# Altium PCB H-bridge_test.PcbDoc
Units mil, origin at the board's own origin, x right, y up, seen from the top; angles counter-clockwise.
Board outline 2420 x 2070 mil, 2 copper layers (Top Layer, Bottom Layer); 25 components, 24 nets, 89 pads, 74 vias.
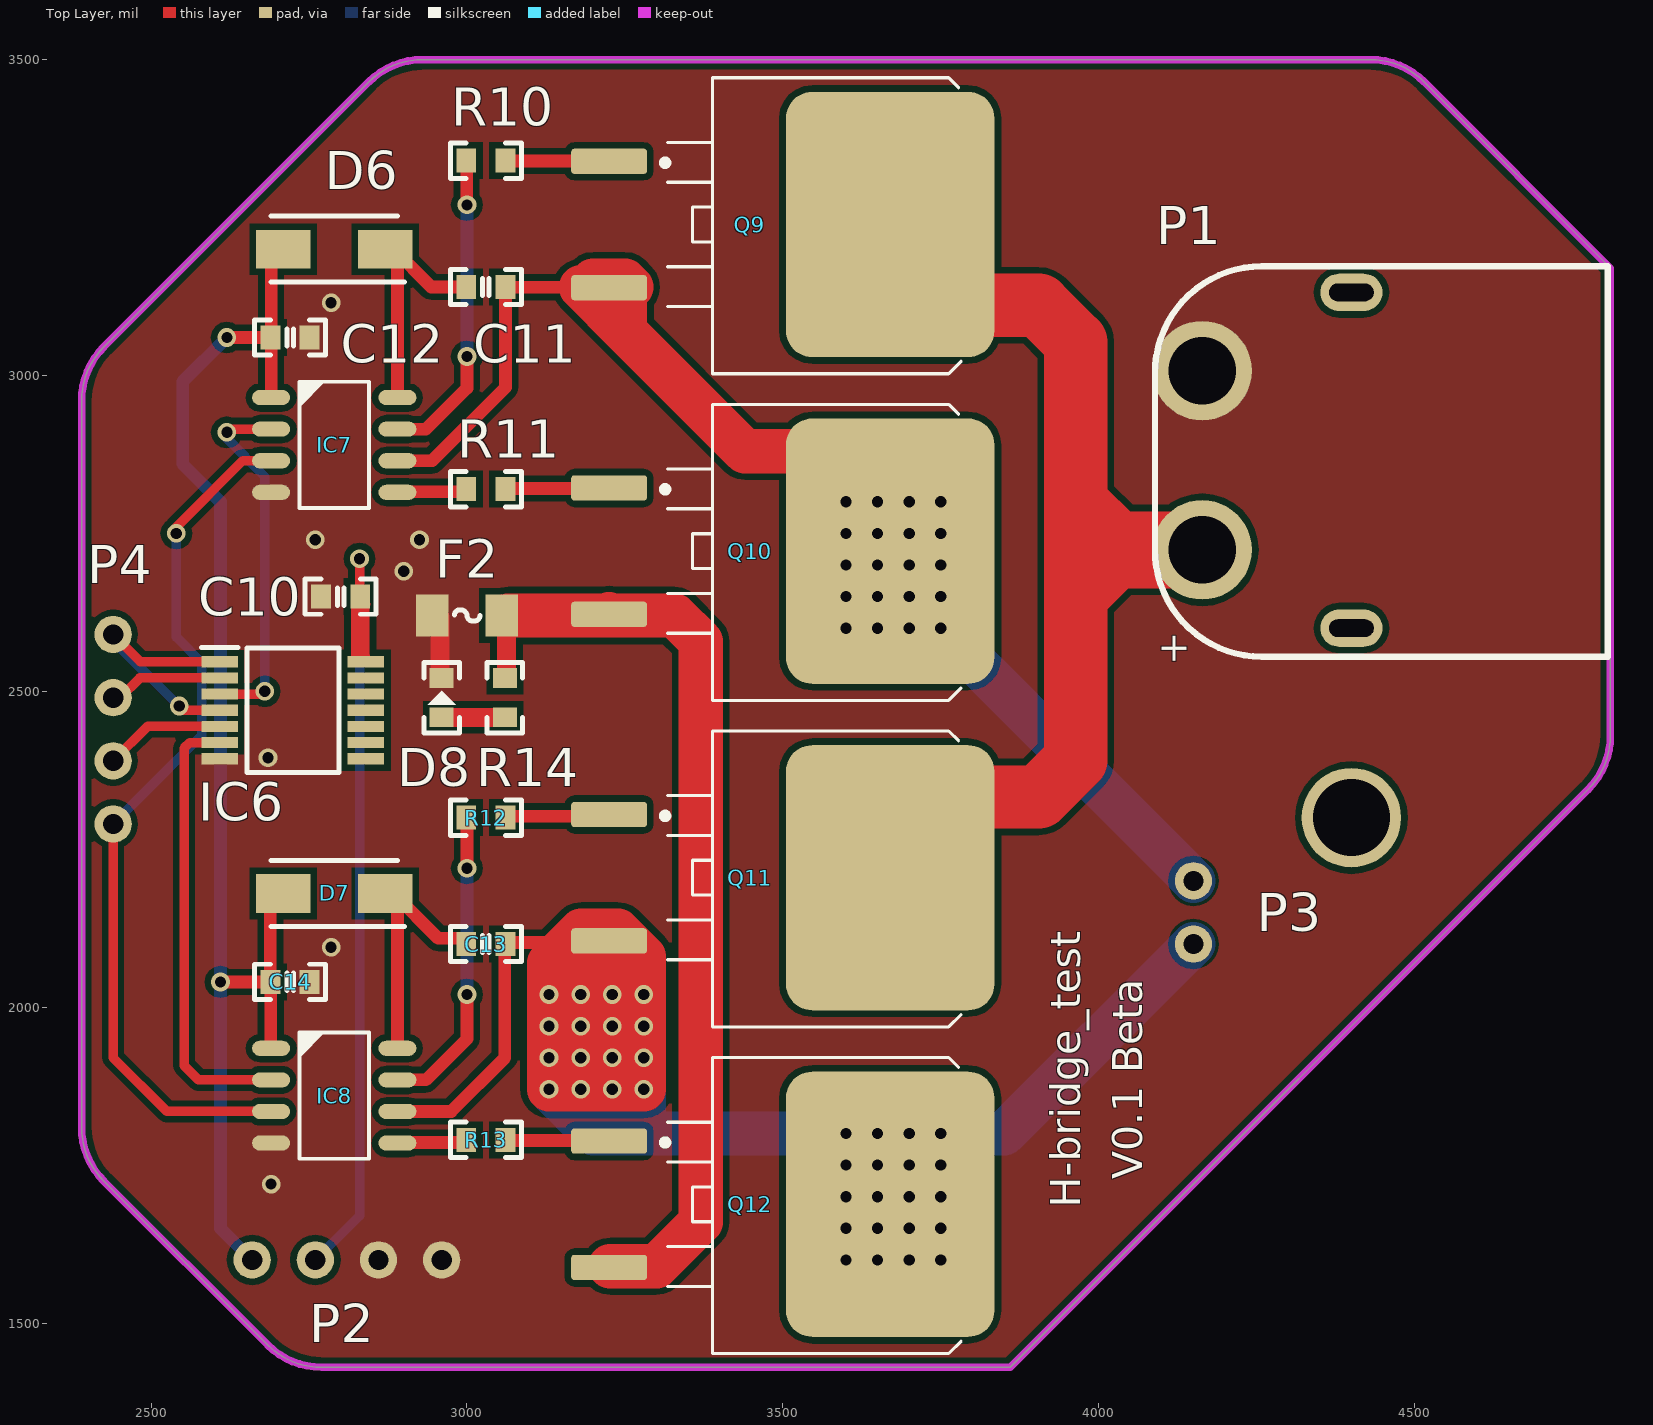
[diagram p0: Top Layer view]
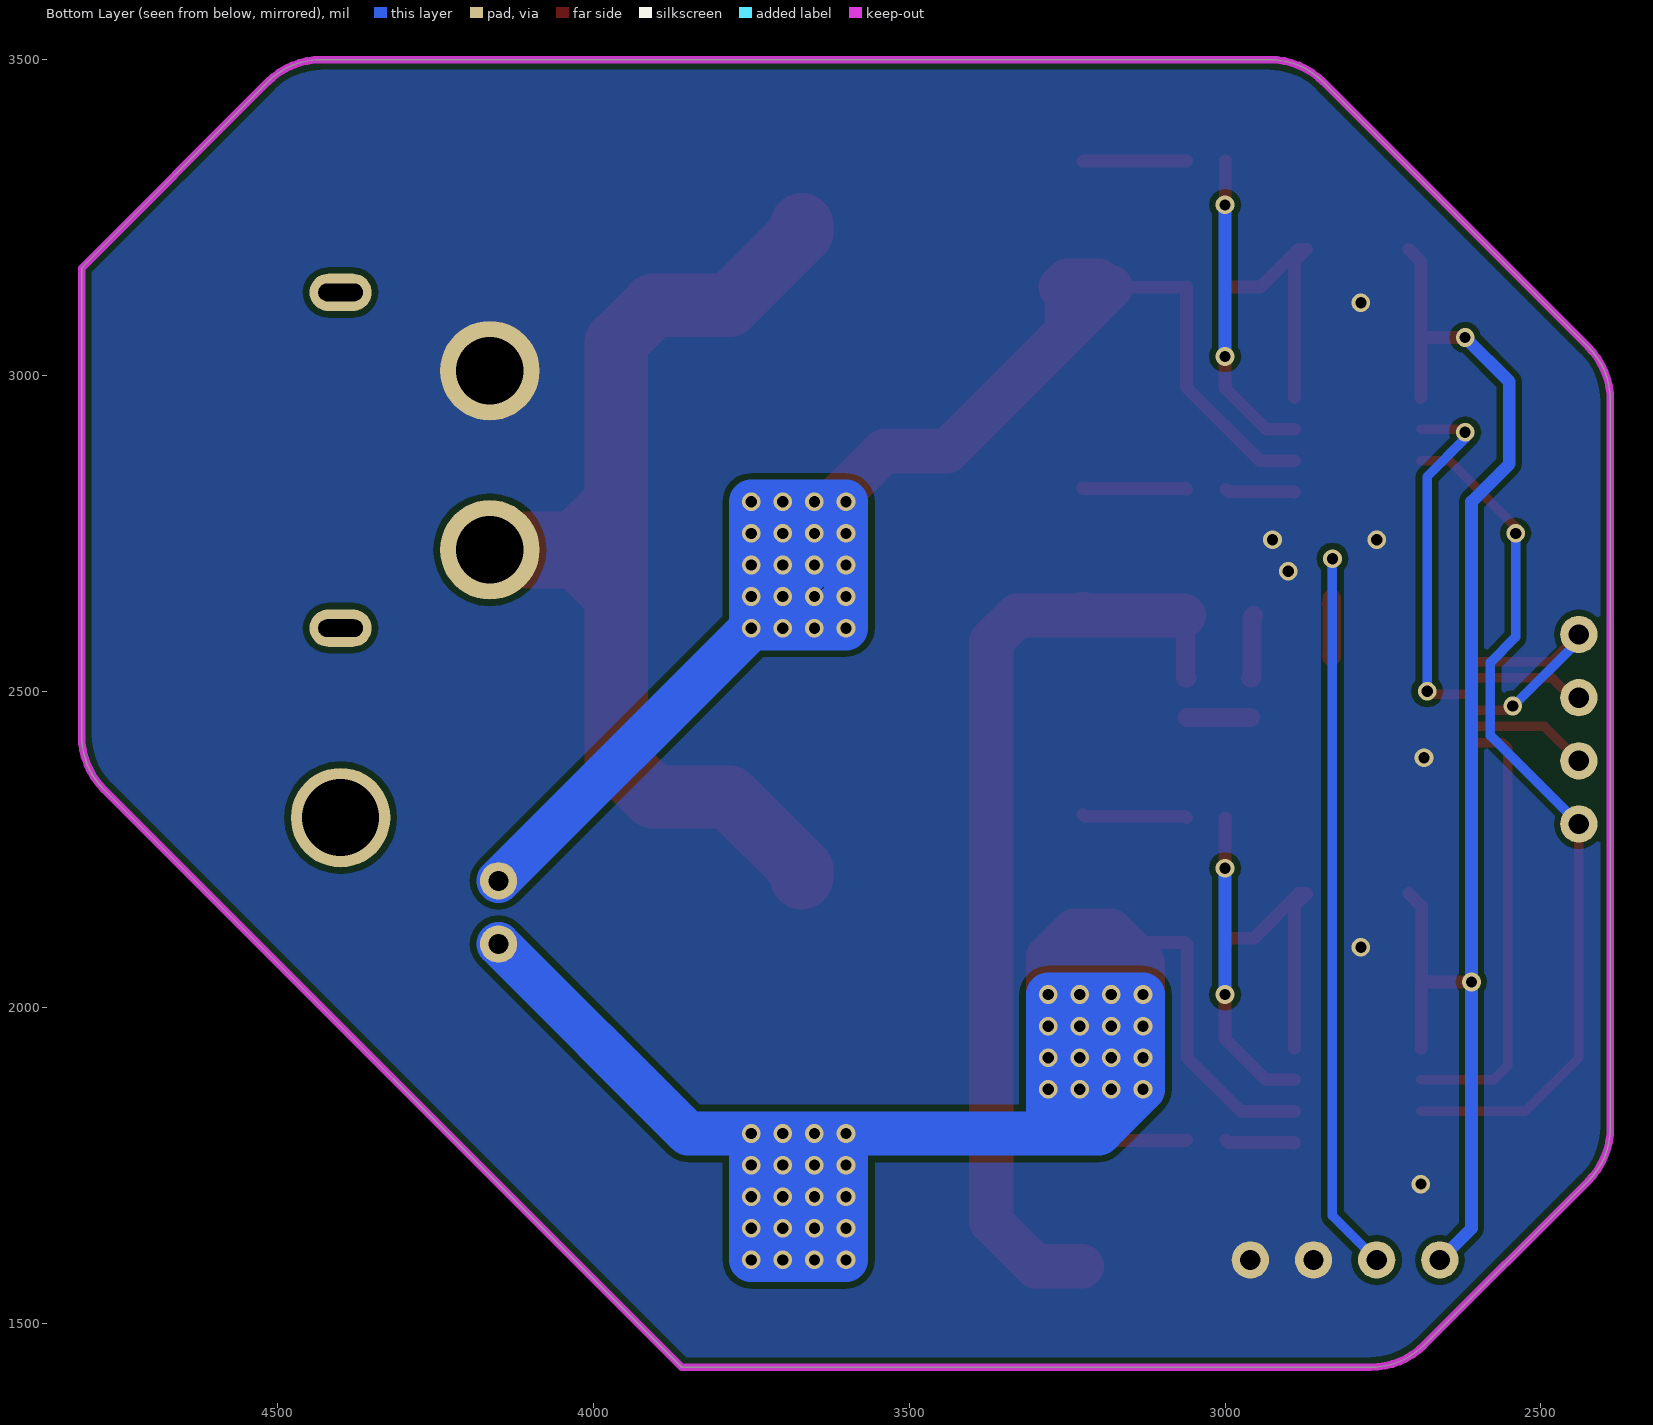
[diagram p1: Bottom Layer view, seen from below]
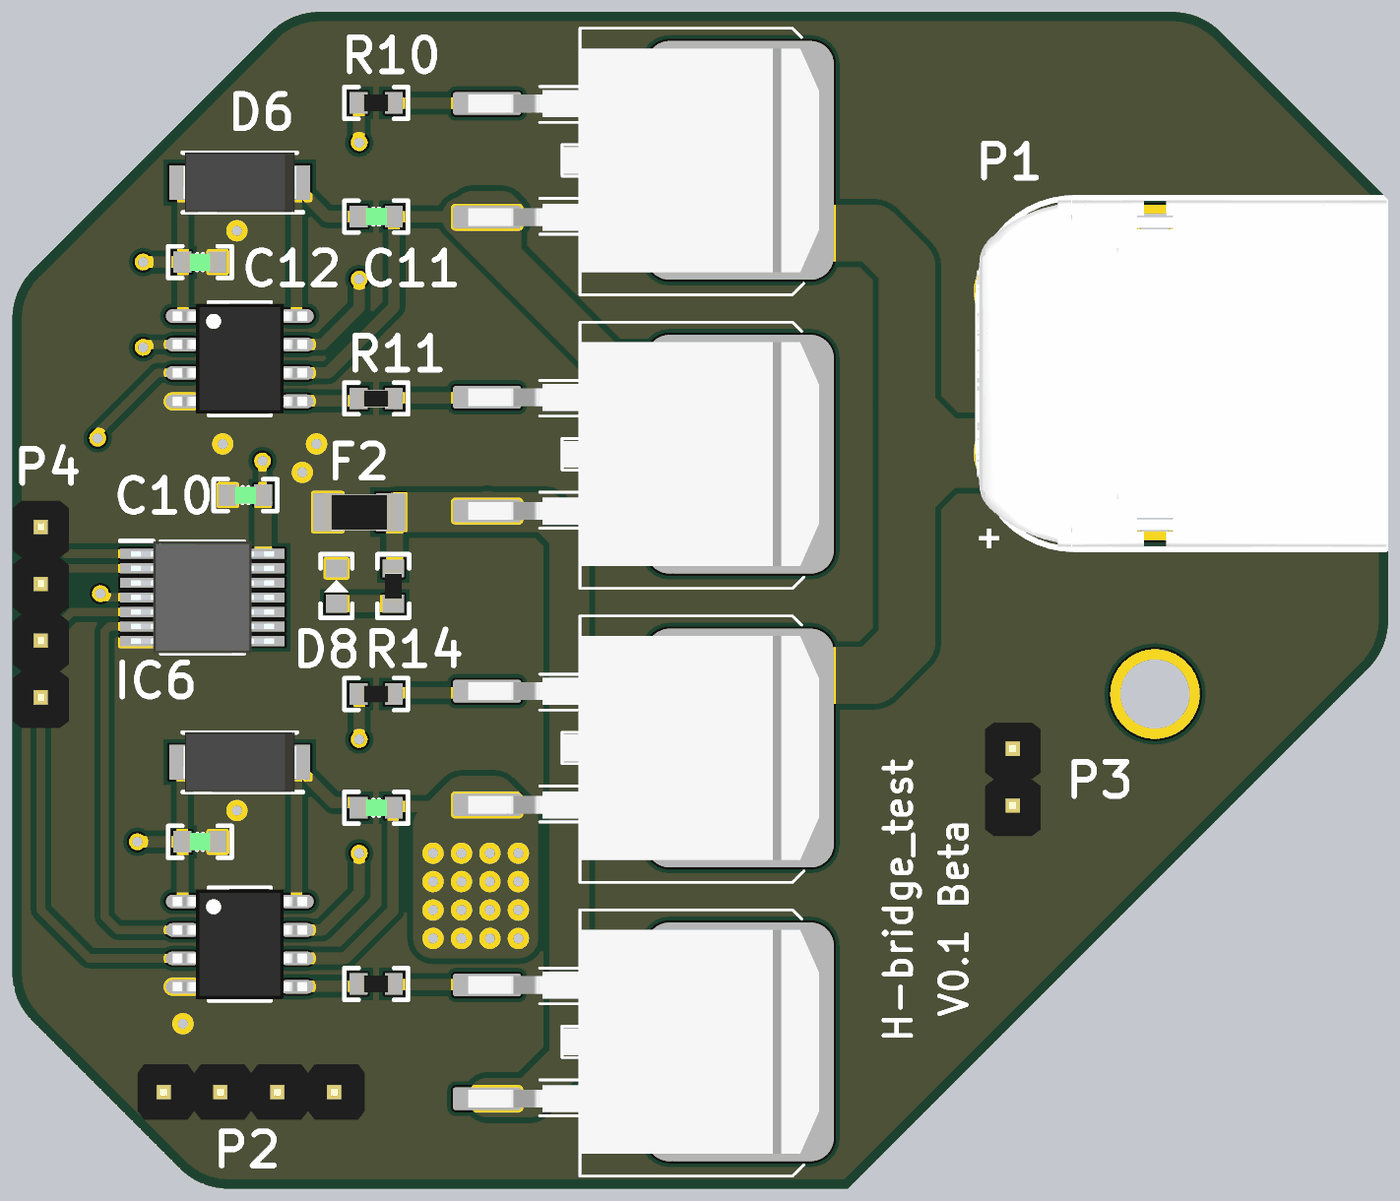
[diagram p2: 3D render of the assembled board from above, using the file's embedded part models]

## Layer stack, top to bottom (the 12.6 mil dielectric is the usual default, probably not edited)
Top Solder: solder mask 0.4, Solder Resist, Dk 3.5
Top Layer: signal copper 1.4
Dielectric 1: dielectric 12.6, FR-4, Dk 4.8
Bottom Layer: signal copper 1.4
Bottom Solder: solder mask 0.4, Solder Resist, Dk 3.5

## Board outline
2425.36,1724.64 2684.64,1465.36 ccw(c2770,1550.71) 2770,1430 3860,1430 4774.64,2344.64 ccw(c4689.29,2430) 4810,2430 4810,3170 4515.36,3464.64 ccw(c4430,3379.29) 4430,3500 2930,3500 ccw(c2930,3379.29) 2844.64,3464.64 2425.36,3045.36 ccw(c2510.71,2960) 2390,2960 2390,1810 ccw(c2510.71,1810)

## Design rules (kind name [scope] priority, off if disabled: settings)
Clearance [All] p1: gap=10 ignorepadtopadclearanceinfootprint=FALSE except(0: Arc-Hole Track-Hole SMDPad-Hole THPad-Hole Via-Hole Fill-Hole Poly-Hole Region-Hole Text-Hole)
PlaneConnect [All] p1: planeconnectstyle=Direct reliefexpansion=20 reliefentries=4 reliefconductorwidth=10 reliefairgap=10
PolygonConnect [All] p1: connectstyle=Direct reliefconductorwidth=10 reliefentries=4 polygonreliefangle="90 Angle" airgapwidth=10
RoutingVias [All] p1: holewidth=17.72 width=29.53 viastyle="Through Hole" minholewidth=17.72 minwidth=29.53 maxholewidth=17.72 maxwidth=29.53
SolderMaskExpansion [All] p1: expansion=4 istentingtop=FALSE
Width [All] p1: maxlimit=100 minlimit=15 preferedwidth=15
29 further rules are at their usual default settings.

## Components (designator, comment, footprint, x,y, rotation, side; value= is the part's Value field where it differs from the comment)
C10 "100nF" CAP-0603 2800,2650 r0 top
C11 "1uF/25V" CAP-0603 3030,3140 r0 top
C12 "100nF" CAP-0603 2720,3060 r180 top
C13 "1uF/25V" CAP-0603 3030,2100 r0 top
C14 "100nF" CAP-0603 2720,2040 r180 top
D6 "SS14" DO-214AC_SMA 2790,3200 r180 top
D7 "SS14" DO-214AC_SMA 2790,2180 r180 top
D8 "LED-RED" LED-0603 2960,2490 r90 top
F2 "JFC1206-2300FS" FUSE_1206 3000,2620 r180 top
IC6 "SN74HC08PW" TSSOP14 2724.33,2470 r0 top
IC7 "IR2104S" SOIC_8 2790,2890 r270 top
IC8 "IR2104S" SOIC_8 2790,1860 r270 top
P1 "XT30/60" XT60PW-M 4163.78,3007.48 r270 top
P2 "HDR1x4_2.54" HDR1x4_2.54_180 2660,1600 r90 top
P3 "HDR1x2_2.54" HDR1X2_2.54_180 4150,2200 r0 top
P4 "HDR1x4_2.54" HDR1x4_2.54_180 2440,2590 r0 top
Q9 "IRF3205S" D2PAK-3 3447.5,3238.89 r180 top
Q10 "IRF3205S" D2PAK-3 3447.5,2721.95 r180 top
Q11 "IRF3205S" D2PAK-3 3447.5,2205 r180 top
Q12 "IRF3205S" D2PAK-3 3447.5,1688.05 r180 top locked
R10 "51R" R-0603 3030,3340 r0 top
R11 "51R" R-0603 3030,2820 r0 top
R12 "51R" R-0603 3030,2300 r0 top
R13 "51R" R-0603 3030,1790 r0 top
R14 "4.7k" R-0603 3060,2490 r270 top

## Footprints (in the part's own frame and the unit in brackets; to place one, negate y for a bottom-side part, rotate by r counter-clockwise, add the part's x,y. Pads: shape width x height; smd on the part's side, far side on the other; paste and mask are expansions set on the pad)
CAP-0603 [mm]
  rect 0.8x0.96 smd: 1(-0.79,0) 2(0.79,0)
  silkscreen extent -1.42,-0.71 1.42,0.71, body extent -0.76,-0.39 0.76,0.39, height 0.9
D2PAK-3 [mil] "D-PAK/TO-263-3; 3 Leads (1 Cropped); Body 14.7 (inc. leads) x 10.2 mm (LxW max)"
  round 20 on Mech15: 0(0,0)
  rrect25% 120x40 smd: 1(222.5,-100) 2(222.5,100)
  rrect25% 330x420 smd: 3(-222.5,0)
  silkscreen extent -335,-232 139,236, body extent -361,-197 256,197, height 189
DO-214AC_SMA [mm]
  rect 2.2x1.55 smd: 1(2.05,0) 2(-2.05,0)
  silkscreen extent -2.83,-1.33 2.55,1.33, body extent -2.55,-1.33 2.55,1.33, height 2.29
FUSE_1206 [mm]
  rect 1.3x1.7 smd: 1(-1.4,0) 2(1.4,0)
  silkscreen extent -0.53,-0.23 0.51,0.23, body extent -1.6,-0.8 1.6,0.8, height 1.01
HDR1X2_2.54_180 [mm]
  round 1.5 hole 0.813: 1(0,0) 2(0,-2.54)
  body extent -1.25,-3.81 1.25,1.27, height 8.2
HDR1x4_2.54_180 [mm]
  round 1.5 hole 0.813: 1(0,0) 2(0,-2.54) 3(0,-5.08) 4(0,-7.62)
  body extent -1.25,-8.89 1.25,1.27, height 8.2
LED-0603 [mm]
  rect 0.8x0.96 smd: 1(-0.79,0) 2(0.79,0)
  silkscreen extent -1.42,-0.71 1.42,0.71, body extent -0.81,-0.4 0.81,0.4, height 0.6
R-0603 [mm]
  rect 0.8x0.96 smd: 1(-0.79,0) 2(0.79,0)
  silkscreen extent -1.42,-0.71 1.42,0.71, body extent -0.76,-0.38 0.76,0.38, height 0.41
SOIC_8 [mil]
  oval 24x60 smd: 1(-75,-100.02) 2(-25,-100.02) 3(25,-100.02) 4(75,-100.02) 5(75,99.98) 6(25,99.98) 7(-25,99.98) 8(-75,99.98)
  silkscreen extent -100,-55 100,55, body extent -96,-118 96,118, height 69
TSSOP14 [mm]
  rect 1.475x0.45 smd: 1(-2.938,1.95) 2(-2.938,1.3) 3(-2.938,0.65) 4(-2.938,0) 5(-2.938,-0.65) 6(-2.938,-1.3) 7(-2.938,-1.95) 8(2.938,-1.95) 9(2.938,-1.3) 10(2.938,-0.65) 11(2.938,0) 12(2.938,0.65) 13(2.938,1.3) 14(2.938,1.95)
  silkscreen extent -3.67,-2.5 1.85,2.52, body extent -3.2,-2.5 3.2,2.5, height 1.2
XT60PW-M [mm]
  oval 1.5x2.5 hole 0.7 slot 1.8 at 90 deg: 0(-3.15,6) 0(10.35,6)
  round 4 hole 2.7: 1(7.2,0) 2(0,0)
  silkscreen extent -4.2,-1.9 11.5,16.3, body extent -4.3,-1.95 11.6,16.35, height 8.45

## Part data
C10 C11 C12 C13 C14: library part CAP, "贴片电容", Package=0402, SuppliersPartNumber=C52923
D6 D7: library part DIODE, "二极管", Package=SMA(DO-214AC), SuppliersPartNumber=C22452
D8: library part LED, "发光二极管", Package=0603, SuppliersPartNumber=C2290
F2: library part Fuse, "一次性贴片保险丝"
IC6: "Integrated Circuit", Arrow Part Number=SN74HCT08PW, Manufacturer_Name="Texas Instruments", Mouser Part Number=595-SN74HCT08PW
IC7 IC8: "Integrated Circuit", Manufacturer_Name=Infineon
P2 P3 P4: "Header"
Q9 Q10 Q11 Q12: library part N-MOS, "N 沟道 MOS", Manufacturer_Name=Nexperia, Manufacturer_Part_Number=SI2302DS, Mouser Part Number=N/A, RS Part Number=7983053P
R10 R11 R12 R13 R14: library part RES, "贴片电阻", Package=0805, SuppliersPartNumber=C17798

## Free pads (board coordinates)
  round 157.48 hole 122.05: 2(4400,2300)

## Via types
v1: diameter 29.53, hole 17.72, Top Layer to Bottom Layer, 74 vias

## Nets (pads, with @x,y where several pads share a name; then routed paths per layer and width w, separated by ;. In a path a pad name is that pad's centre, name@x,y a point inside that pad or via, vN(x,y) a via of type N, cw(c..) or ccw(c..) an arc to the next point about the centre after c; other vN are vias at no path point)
5V: C10.2 IC6.14 P2.2 | length 1377.3
  Top Layer w15: v1(2830,2710) 2830,2581.1 2831.1,2580 ; C10.2 2831.1,2646.85 C10.2@2840,2637.95
  Top Layer w30: C10.2@2831.1,2646.85 2831.1,2580 2831.1,2555.67 IC6.14@2831.73,2555.04
  Bottom Layer w15: P2.2 2830,1670 v1(2830,2710)
12V: C12.2 C14.2 D6.1 D7.1 IC7.1 IC8.1 P2.1 | length 2179.3
  Top Layer w20: v1(2610,2040) C14.2 ; v1(2620,3060) C12.2 ; IC8.1 2689.44,1935.54 2689.44,2039.46 C14.2 ; IC7.1 2689.98,3180.69 D6.1 ; D7.1 2688.9,2159.61 C14.2
  Bottom Layer w20: v1(2620,3060) 2550,2990 2550,2860 2610,2800 v1(2610,2040) 2610,1650 P2.1
DIR1A: IC6.2 P4.2 | length 181.6
  Top Layer w15: P4.2 2451.22,2490 2482.4,2521.18 IC6.2
DIR1B: IC6.5 P4.3 | length 191.2
  Top Layer w15: P4.3 2494.41,2444.41 IC6.5
FUSE: F2.1 Q10.2 Q12.2 R14.1 | length 1516.6
  Top Layer w30: R14.1 3061.81,2521.1 3062.56,2521.85 F2.1@3062.56,2617.44 ; F2.1@3072.56,2612.44 F2.1@3075.12,2615
  Top Layer w70: F2.1@3065.12,2620 3223.05,2620 Q10.2 3226.95,2620 3328.99,2620 3370,2578.99 3370,1660 3300,1590 Q12.2@3226.95,1590
GND: C10.1 C12.1 C14.1 D8.2 F2.2 IC6.7 IC7.4 IC8.4 P1.2 P2.3 P2.4 | length 102.1
  Top Layer w30: F2.2@2954.88,2620 2957.44,2617.44 2957.44,2521.85 2958.19,2521.1 D8.2
  other v1: 2690,1720 2785,2095 2685,2395 2900,2690 2760,2740 2925,2740 2785,3115
M1A: C11.2 IC7.6 P3.1 Q9.2 Q10.3 | length 3108.5
  Top Layer w20: IC7.6 2945,2865 3061.1,2981.1 C11.2 3061.66,3139.45 3180.55,3139.45 3224.45,3139.45 Q9.2
  Top Layer w70: Q9.2@3180.55,3139.45 3250,3070 ; Q9.2@3200,3150 Q9.2@3213.89,3150 ; Q9.2@3224.45,3139.45 Q9.2@3213.89,3150 ; Q9.2 3226.11,3140 Q9.2@3250,3140 ; Q10.3 3670,2750.48 3540.48,2880 3440,2880 3250,3070 ; Q9.2@3213.89,3150 Q9.2@3250,3150 ; 3250,3070 Q9.2@3250,3140 ; Q9.2@3250,3140 Q9.2@3250,3150 ; Q9.2@3250,3140 3260,3140 Q9.2@3250,3150
  Bottom Layer w70: v1(3650,2750) v1(3650,2700) v1(3700,2650) 3725,2625 ; v1(3700,2700) v1(3700,2750) v1(3700,2800) ; P3.1 v1(3750,2600) ; v1(3600,2650) 3625,2625 3725,2625 ; v1(3600,2650) v1(3600,2700) v1(3600,2750) v1(3600,2800) v1(3650,2800) v1(3700,2800) ; v1(3600,2650) v1(3600,2600) v1(3650,2600) v1(3700,2600) v1(3750,2600) ; v1(3700,2800) v1(3750,2800) v1(3750,2750) v1(3750,2700) v1(3750,2650) v1(3750,2600) ; 3725,2625 v1(3750,2600)
  other v1: 3650,2650
M1B: C13.2 IC8.6 P3.2 Q11.2 Q12.3 | length 5371.6
  Top Layer w20: IC8.6 2975,1835 3060,1920 3060,2098.9 C13.2 3063.6,2102.5 3162.5,2102.5 3212.5,2102.5 3222.5,2102.5 Q11.2
  Top Layer w70: v1(3180,1920) v1(3230,1920) ; Q11.2@3222.5,2102.5 3230,2095 v1(3230,2020) ; v1(3230,1970) v1(3180,1970) v1(3130,1970) ; v1(3130,1970) v1(3130,2020) ; v1(3130,1970) v1(3130,1920) v1(3130,1870) v1(3180,1870) v1(3230,1870) v1(3280,1870) v1(3280,1920) v1(3280,1970) v1(3280,2020) ; v1(3130,2020) 3212.5,2102.5 3215,2105 Q11.2 3235,2105 3280,2060 ; v1(3130,2020) 3130,2070 3162.5,2102.5 3181.01,2121.01 3238.99,2121.01 3280,2080 3280,2060 ; v1(3130,2020) v1(3180,2020) v1(3230,2020) ; v1(3230,2020) v1(3280,2020) ; v1(3280,2020) 3280,2060
  Bottom Layer w70: v1(3230,1970) v1(3180,2020) ; P3.2 3850,1800 v1(3750,1800) ; v1(3130,1870) 3185.48,1814.52 ; v1(3130,1870) v1(3180,1870) v1(3230,1870) ; v1(3130,1870) v1(3130,1920) ; v1(3130,1920) v1(3180,1920) v1(3230,1920) ; v1(3130,1920) v1(3130,1970) v1(3130,2020) ; v1(3130,2020) v1(3180,1970) v1(3230,1920) ; v1(3130,2020) v1(3180,2020) ; v1(3180,2020) v1(3230,2020) 3250,2020 ; 3185.48,1814.52 3200,1800 3265.48,1800 ; 3185.48,1814.52 3251.31,1814.52 ; v1(3230,1870) v1(3230,1920) ; v1(3230,1870) 3251.31,1870 ; 3250,2020 v1(3280,2020) v1(3280,1970) v1(3280,1920) v1(3280,1870) ; 3250,2020 3251.31,2018.69 3251.31,1870 ; 3251.31,1814.52 3251.31,1870 ; 3251.31,1814.52 3251.31,1814.17 3265.48,1800 ; 3251.31,1814.52 3280,1814.52 ; 3251.31,1870 v1(3280,1870) ; 3265.48,1800 v1(3600,1800) ; 3265.48,1800 3280,1814.52 ; 3280,1814.52 v1(3280,1870) ; v1(3600,1800) v1(3600,1750) v1(3600,1700) v1(3600,1650) v1(3600,1600) v1(3650,1600) ; v1(3600,1800) v1(3650,1800) ; v1(3650,1600) v1(3650,1650) v1(3650,1700) v1(3650,1750) v1(3650,1800) ; v1(3650,1600) v1(3700,1600) ; v1(3650,1800) v1(3700,1800) ; v1(3700,1600) v1(3700,1650) v1(3700,1700) v1(3700,1750) v1(3700,1800) ; v1(3700,1600) v1(3750,1600) v1(3750,1650) v1(3750,1700) v1(3750,1750) v1(3750,1800) ; v1(3700,1800) v1(3750,1800)
NetC11_1: C11.1 D6.2 IC7.8 | length 396
  Top Layer w20: IC7.8 2889.98,3180.72 D6.2 2883.5,3200 2943.5,3140 C11.1
NetC13_1: C13.1 D7.2 IC8.8 | length 416.2
  Top Layer w20: IC8.8 2889.98,2160.72 D7.2 2883.5,2180 2954.61,2108.9 2993.15,2108.9 2998.9,2103.15 C13.1
NetD8_A: D8.1 R14.2 | length 100
  Top Layer w30: D8.1 R14.2
NetIC7_5: IC7.5 R11.1 | length 111
  Top Layer w20: IC7.5 2890.75,2815.76 2994.66,2815.76 R11.1
NetIC7_7: IC7.7 R10.1 | length 497.4
  Top Layer w20: IC7.7 2935,2915 3000,2980 v1(3000,3030) ; R10.1 2999.45,3339.45 2999.45,3270.55 v1(3000,3270)
  Bottom Layer w20: v1(3000,3030) v1(3000,3270)
NetIC8_5: IC8.5 R13.1 | length 111
  Top Layer w20: IC8.5 2890.75,1785.76 2994.66,1785.76 R13.1
NetIC8_7: IC8.7 R12.1 | length 487.4
  Top Layer w20: IC8.7 2935,1885 3000,1950 v1(3000,2020) ; R12.1 3000,2298.9 v1(3000,2220)
  Bottom Layer w20: v1(3000,2020) v1(3000,2220)
NetQ9_1: Q9.1 R10.2 | length 164.4
  Top Layer w20: R10.2 3061.66,3339.45 3224.45,3339.45 Q9.1
NetQ10_1: Q10.1 R11.2 | length 164.7
  Top Layer w20: R11.2 3062.08,2820.97 3224.03,2820.97 Q10.1
NetQ11_1: Q11.1 R12.2 | length 166
  Top Layer w20: R12.2 3063.6,2302.5 3222.5,2302.5 Q11.1
NetQ12_1: Q12.1 R13.2 | length 164.7
  Top Layer w20: R13.2 3062.08,1789.03 3224.03,1789.03 Q12.1
PWM1: IC6.1 IC6.4 P4.1 | length 410.4
  Top Layer w15: P4.1 2483.23,2546.77 IC6.1 ; v1(2544.76,2476.67) 2551.44,2470 IC6.4
  Bottom Layer w15: P4.1 2440,2580.6 2543.93,2476.67 v1(2544.76,2476.67)
PWM1A: IC6.3 IC7.2 | length 580.1
  Top Layer w15: IC6.3 2671.66,2495.59 2676.07,2500 v1(2680,2500) ; v1(2620,2910) 2625,2915 IC7.2
  Bottom Layer w15: v1(2620,2910) 2620,2900 2680,2840 v1(2680,2500)
PWM1B: IC6.6 IC8.2 | length 709.3
  Top Layer w15: IC6.6 2561.18,2418.82 2552.39,2410.03 2552.39,1907.61 2575,1885 IC8.2
SD: IC7.3 IC8.3 P4.4 | length 1393.2
  Top Layer w15: P4.4 2440,1920 2525,1835 IC8.3 ; v1(2540,2750) 2540,2760 2645,2865 IC7.3
  Bottom Layer w15: P4.4 2580,2430 2580,2545.74 2540,2585.74 v1(2540,2750)
VM: P1.1 Q9.3 Q11.3 | length 2080.2
  Top Layer w100: Q11.3 3670,2217.77 3785,2332.77 3905.2,2332.77 3963.78,2391.35 3963.78,2650 ; Q9.3 3670,3226.13 3785,3111.13 3905.2,3111.13 3963.78,3052.55 3963.78,2800 ; 3963.78,2650 3963.78,2724.02 ; 3963.78,2650 4026.8,2713.02 4152.78,2713.02 P1.1 ; 3963.78,2724.02 3963.78,2800 ; 3963.78,2724.02 P1.1 ; 3963.78,2800 4028.77,2735.01 4152.78,2735.01 P1.1
pads on no net: IC6.8 IC6.9 IC6.10 IC6.11 IC6.12 IC6.13 P1.0 Q9.0 Q10.0 Q11.0 Q12.0

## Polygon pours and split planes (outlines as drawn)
GND on Bottom Layer "GND_L02_P000" (solid, remove dead copper, pour order 0): 2005,3685 2005,1285 5005,1285 5105,1385 5105,3685
GND on Top Layer "GND_L01_P001" (solid, remove dead copper, pour order 1): 1805,3785 1805,885 5305,885 5305,3785

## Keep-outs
Keep-Out Layer:
  lines w12: 2390,1810 ccw(c2510.71,1810) 2425.36,1724.64 2684.64,1465.36 ccw(c2770,1550.71) 2770,1430 3860,1430 4774.64,2344.64 ccw(c4689.29,2430) 4810,2430 4810,3060 4810,3170 4515.36,3464.64 ccw(c4430,3379.29) 4430,3500 2930,3500 ccw(c2930,3379.29) 2844.64,3464.64 2425.36,3045.36 ccw(c2510.71,2960) 2390,2960 2390,1810

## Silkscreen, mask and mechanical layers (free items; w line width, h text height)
Top Overlay:
  text "V0.1 Beta" at 4068.61,1727.87 h47.24 r90
  text "H-bridge_test" at 3970.74,1682.87 h47.24 r90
